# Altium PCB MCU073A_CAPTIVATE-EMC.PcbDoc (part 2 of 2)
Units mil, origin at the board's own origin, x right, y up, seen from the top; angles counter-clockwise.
Board outline 5374.02 x 3444.88 mil, 2 copper layers (Top Layer, Bottom Layer), stack 62 mil thick; 125 components, 86 nets, 448 pads, 154 vias.
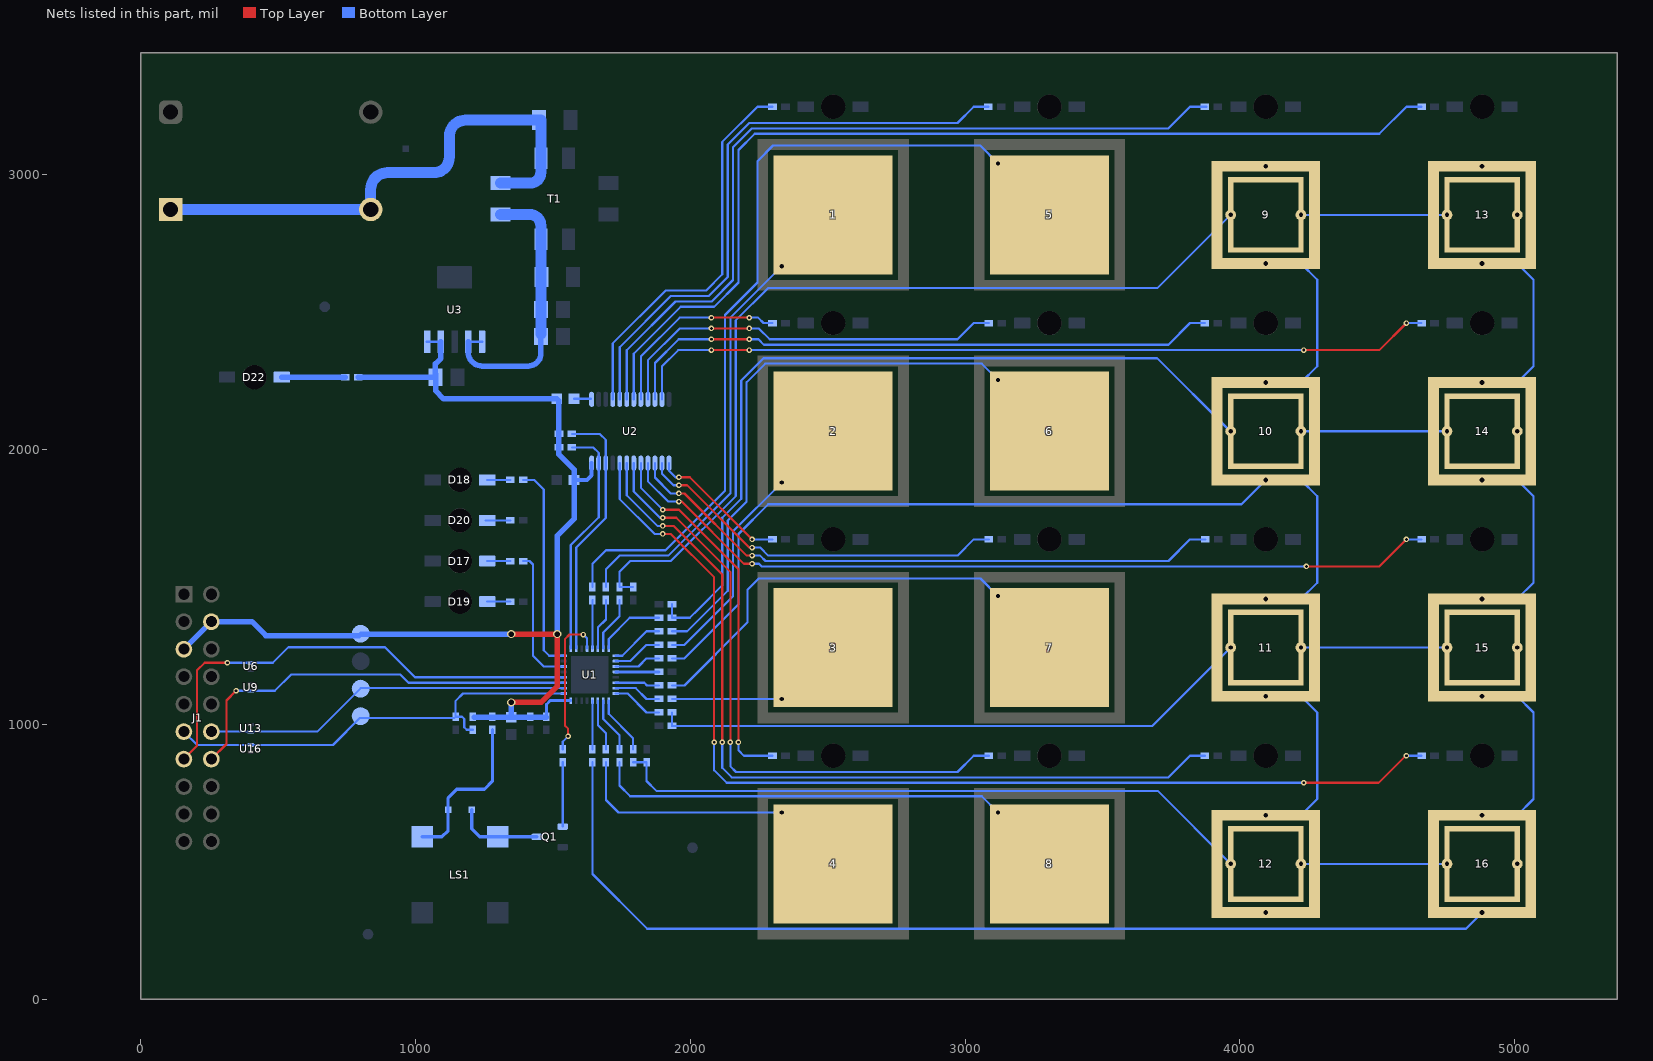
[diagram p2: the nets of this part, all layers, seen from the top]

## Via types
v1: diameter 30, hole 15, Top Layer to Bottom Layer, tented both sides, 102 vias
v2: diameter 20, hole 10, Top Layer to Bottom Layer, tented both sides, 34 vias
v3: diameter 30, hole 20, Top Layer to Bottom Layer, tented both sides, 13 vias
v4: diameter 19.68, hole 7.87, Top Layer to Bottom Layer, 5 vias

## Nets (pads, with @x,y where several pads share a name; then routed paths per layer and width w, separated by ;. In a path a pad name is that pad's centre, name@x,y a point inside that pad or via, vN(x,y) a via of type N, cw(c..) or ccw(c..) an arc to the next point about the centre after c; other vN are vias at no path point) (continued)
NetC12_1: C12.1 C13.1 C14.1 R39.2 T1.4 U3.1 U3.2 | length 1032.9
  Bottom Layer w10: U3.2@1191.73,2392.72 U3.1@1241.73,2392.72
  Bottom Layer w20: U3.2@1191.73,2392.72 1191.73,2354.13 ccw(c1241.73,2354.13) 1241.73,2304.13 1409.77,2304.13 ccw(c1409.77,2350.42) 1456.06,2350.42 C14.1@1456.06,2411.42
  Bottom Layer w40: R39.2@1309.05,2856.3 1414.56,2856.3 cw(c1414.56,2814.95) 1455.91,2814.95 T1.4@1455.91,2765.75 C14.1@1455.91,2421.42
NetD17_2: D17.2 R28.2 | length 83.7
  Bottom Layer w8: D17.2@1260.83,1594.49 R28.2@1344.49,1594.49
NetD18_2: D18.2 R36.2 | length 83.7
  Bottom Layer w8: D18.2@1260.83,1889.76 R36.2@1344.49,1889.76
NetD19_2: D19.2 R37.2 | length 83.7
  Bottom Layer w8: D19.2@1260.83,1446.85 R37.2@1344.49,1446.85
NetD20_2: D20.2 R38.2 | length 89.6
  Bottom Layer w8: D20.2@1254.92,1742.13 R38.2@1344.49,1742.13
NetD22_2: D22.2 R40.1 | length 231.3
  Bottom Layer w20: D22.2@512.79,2263.78 R40.1@744.09,2263.78
NetD23_1: D23.1 LS1.2 Q1.3 | length 317.6
  Bottom Layer w12: D23.1@1204.72,688.98 1204.72,619.59 1233.76,590.55 LS1.2@1299.21,590.55 Q1.3@1440.94,590.55
NetD23_2: D23.2 LS1.1 R42.1 | length 597.4
  Bottom Layer w12: LS1.1@1023.62,590.55 1095.97,590.55 1118.11,612.69 D23.2@1118.11,688.98 1118.11,732.28 1149.61,763.78 1250.76,763.78 1279.53,792.55 R42.1@1279.53,980.32
NetQ1_1: Q1.1 R43.2 | length 234.3
  Bottom Layer w8: Q1.1@1535.43,627.95 R43.2@1535.43,862.2
NetR1_1: R1.1 U1.13 | length 177.2
  Bottom Layer w8: U1.13@1643.7,1275.59 R1.1@1643.7,1452.76
NetR2_1: R2.1 U1.14 | length 189.4
  Bottom Layer w8: U1.14@1663.39,1275.59 1663.39,1352.35 1692.91,1381.88 R2.1@1692.91,1452.76
NetR3_1: R3.1 U1.15 | length 201.6
  Bottom Layer w8: U1.15@1683.07,1275.59 1683.07,1334.07 1742.13,1393.13 R3.1@1742.13,1452.76
NetR4_1: R4.1 U1.16 | length 250.3
  Bottom Layer w8: U1.16@1702.76,1275.59 1702.76,1311.02 1779.53,1387.79 R4.1@1885.83,1387.79
NetR5_1: R5.1 U1.17 | length 194.2
  Bottom Layer w8: U1.17@1728.35,1250 1751.97,1250 1840.55,1338.58 R5.1@1885.83,1338.58
NetR6_1: R6.1 U1.18 | length 181.9
  Bottom Layer w8: U1.18@1728.35,1230.31 1781.5,1230.31 1840.55,1289.37 R6.1@1885.83,1289.37
NetR7_1: R7.1 U1.19 | length 169.7
  Bottom Layer w8: U1.19@1728.35,1210.63 1811.02,1210.63 1840.55,1240.16 R7.1@1885.83,1240.16
NetR8_1: R8.1 U1.22 | length 161.6
  Bottom Layer w8: U1.22@1728.35,1151.57 1832.68,1151.57 1842.52,1141.73 R8.1@1885.83,1141.73
NetR9_1: R9.1 U1.23 | length 173.8
  Bottom Layer w8: U1.23@1728.35,1131.89 1801.18,1131.89 1840.55,1092.52 R9.1@1885.83,1092.52
NetR10_1: R10.1 U1.24 | length 186
  Bottom Layer w8: U1.24@1728.35,1112.2 1771.65,1112.2 1840.55,1043.31 R10.1@1885.83,1043.31
NetR11_1: R11.1 U1.25 | length 213.9
  Bottom Layer w7.87: U1.25@1702.76,1086.61 1702.76,1038.3 1791.34,949.71 R11.1@1791.34,909.45
NetR12_1: R12.1 U1.26 | length 201.6
  Bottom Layer w7.87: U1.26@1683.07,1086.61 1683.07,1019.41 1742.13,960.35 R12.1@1742.13,909.45
NetR13_1: R13.1 U1.27 | length 189.4
  Bottom Layer w7.87: U1.27@1663.39,1086.61 1663.39,997.6 1692.91,968.08
  Bottom Layer w8: R13.1@1692.91,909.45 1692.91,968.08
NetR14_1: R14.1 U1.28 | length 177.2
  Bottom Layer w8: R14.1@1643.7,909.45 U1.28@1643.7,1086.61
NetR17_1: R17.1 U2.4 | length 1424.7
  Bottom Layer w7.87: U2.4@1717.52,2183.07 1717.52,2386.81 1909.45,2578.74 2057.09,2578.74 2116.14,2637.8 2116.14,3120.08 2244.09,3248.03 R17.1@2299.21,3248.03
NetR19_1: R19.1 U2.5 | length 2176.4
  Bottom Layer w7.87: U2.5@1743.11,2183.07 1743.11,2373.03 1929.13,2559.06 2066.93,2559.06 2135.83,2627.95 2135.83,3110.24 2214.57,3188.98
  Bottom Layer w8: 2214.57,3188.98 2972.44,3188.98 3031.5,3248.03 R19.1@3084.65,3248.03
NetR20_1: R20.1 U2.6 | length 2938.3
  Bottom Layer w8: U2.6@1768.7,2183.07 1768.7,2362.21 1945.87,2539.37 2077.56,2539.37 2155.51,2617.32 2155.51,3100.39 2224.41,3169.29 3740.16,3169.29 3818.9,3248.03 R20.1@3872.8,3248.03 R20.1@3877.95,3248.03
NetR21_1: R21.1 U2.7 | length 3688.2
  Bottom Layer w8: U2.7@1794.29,2183.07 1794.29,2349.41 1964.56,2519.68 2086.61,2519.68 2175.2,2608.27 2175.2,3090.51 2234.29,3149.61 4507.87,3149.61 4606.3,3248.03 R21.1@4661.42,3248.03
NetR22_1: R22.1 U2.8 | length 711.8
  Top Layer w8: v2(2076.77,2480.32) v2(2214.57,2480.32)
  Bottom Layer w7.87: U2.8@1819.88,2183.07 1819.88,2338.94 1961.26,2480.32 v2(2076.77,2480.32)
  Bottom Layer w8: v2@2224.41,2480.32 v2(2214.57,2480.32) 2246.65,2480.32 2266.34,2460.63 R22.1@2299.21,2460.63
NetR23_1: R23.1 U2.9 | length 1481.6
  Top Layer w8: v2(2076.77,2440.94) v2(2214.57,2440.94)
  Bottom Layer w7.87: U2.9@1845.47,2183.07 1845.47,2324.8 1961.61,2440.94 v2(2076.77,2440.94)
  Bottom Layer w8: v2@2224.41,2440.94 v2(2214.57,2440.94) 2249.37,2440.94 2288.74,2401.57 2972.44,2401.57 3031.5,2460.63 R23.1@3086.61,2460.63
NetR24_1: R24.1 U2.10 | length 2210.3
  Top Layer w8: v2(2076.77,2401.57) v2(2214.57,2401.57)
  Bottom Layer w7.87: U2.10@1871.06,2183.07 1871.06,2314.96 1957.68,2401.57 v2(2076.77,2401.57)
  Bottom Layer w8: v2(2214.57,2401.57) 2247.96,2401.57 2267.65,2381.89 3740.16,2381.89 3818.9,2460.63 R24.1@3872.8,2460.63
NetR25_1: R25.1 U2.11 | length 2950.1
  Top Layer w8: v2(2076.77,2362.2) v2(2214.57,2362.2) ; v2(4232.28,2362.2) 4507.87,2362.2 v2(4606.3,2460.63)
  Bottom Layer w7.87: U2.11@1896.65,2183.07 1896.65,2303.15 1955.71,2362.2 v2(2076.77,2362.2)
  Bottom Layer w8: v2(2214.57,2362.2) v2(4232.28,2362.2) ; v2(4606.3,2460.63) R25.1@4661.42,2460.63
NetR26_1: R26.1 U2.13 | length 507.9
  Top Layer w8: v2(1958.66,1899.61) 1998.03,1899.61 v2(2224.41,1673.23)
  Bottom Layer w8: U2.13@1922.24,1950.79 1922.24,1923.26 1945.9,1899.61 v2(1958.66,1899.61) ; v2(2224.41,1673.23) R26.1@2299.02,1673.23
NetR27_1: R27.1 U2.14 | length 1376.3
  Top Layer w8: v2(1958.66,1870.08) 1988.19,1870.08 2214.57,1643.7 v2(2224.41,1643.7)
  Bottom Layer w8: U2.14@1896.65,1950.79 1896.65,1912.4 1938.98,1870.08 v2(1958.66,1870.08) ; v2(2224.41,1643.7) 2253.94,1643.7 2283.46,1614.17 2972.44,1614.17 3031.5,1673.23 R27.1@3086.61,1673.23
NetR29_1: R29.1 U2.15 | length 2213.7
  Top Layer w8: v2(1958.66,1840.55) 1978.35,1840.55 2204.72,1614.17 v2(2224.41,1614.17)
  Bottom Layer w8: U2.15@1871.06,1950.79 1871.06,1898.62 1929.13,1840.55 v2(1958.66,1840.55) ; v2(2224.41,1614.17) 2253.94,1614.17 2273.62,1594.49 3740.16,1594.49 3818.9,1673.23 R29.1@3874.02,1673.23
NetR30_1: R30.1 U2.16 | length 3051.1
  Top Layer w8: v2(1958.66,1811.02) 1968.5,1811.02 2194.88,1584.65 v2(2224.41,1584.65) ; v2(4242.13,1574.8) 4507.87,1574.8 v2(4606.3,1673.23)
  Bottom Layer w8: U2.16@1845.47,1950.79 1845.47,1884.84 1919.29,1811.02 v2(1958.66,1811.02) ; v2(2224.41,1584.65) 2249.87,1584.65 2259.71,1574.8 v2(4242.13,1574.8) ; v2(4606.3,1673.23) R30.1@4661.42,1673.23
NetR31_1: R31.1 U2.17 | length 1359.2
  Top Layer w8: v2(1899.61,1781.5) 1958.66,1781.5 2175.2,1564.96 v2(2175.2,935.04)
  Bottom Layer w8: U2.17@1819.88,1950.79 1819.88,1861.22 v2(1899.61,1781.5) ; v2(2175.2,935.04) 2175.2,905.51 2194.88,885.83 R31.1@2299.21,885.83
NetR32_1: R32.1 U2.18 | length 2257.5
  Top Layer w8: v2(1899.61,1751.97) 1948.82,1751.97 2145.67,1555.12 v2(2145.67,935.04)
  Bottom Layer w8: U2.18@1794.29,1950.79 1794.29,1847.44 1889.76,1751.97 v2(1899.61,1751.97) ; v2(2145.67,935.04) 2145.67,847.38 2166.27,826.77 2972.44,826.77 3031.5,885.83 R32.1@3086.61,885.83
NetR33_1: R33.1 U2.19 | length 3091.1
  Top Layer w8: v2(1899.61,1722.44) 1938.98,1722.44 2116.14,1545.28 v2(2116.14,935.04)
  Bottom Layer w8: U2.19@1768.7,1950.79 1768.7,1833.66 1879.92,1722.44 v2(1899.61,1722.44) ; v2(2116.14,935.04) 2116.14,841.89 2150.95,807.09 3740.16,807.09 3818.9,885.83 R33.1@3872.8,885.83
NetR34_2: R34.2 U2.1 | length 62
  Bottom Layer w8: R34.2@1576.77,2185.04 U2.1@1638.78,2185.04
NetR35_1: R35.1 U2.20 | length 3929
  Top Layer w8: v2(1899.61,1692.91) 1929.13,1692.91 2086.61,1535.43 v2(2086.61,935.04) ; v2(4232.28,787.4) 4505.18,787.4 4603.6,885.83 v2(4606.3,885.83)
  Bottom Layer w8: U2.20@1743.11,1950.79 1743.11,1819.88 1870.08,1692.91 v2(1899.61,1692.91) ; v2(2086.61,935.04) 2086.61,833.14 2132.36,787.4 v2(4232.28,787.4) ; v2(4606.3,885.83) R35.1@4661.42,885.83
NOISE: R28.1 U1.6 | length 501.2
  Bottom Layer w8: R28.1@1391.73,1594.49 1414.8,1594.49 1427.16,1582.13 1427.16,1250 1466.53,1210.63 U1.6@1539.37,1210.63
RUN: R36.1 U1.8 | length 755.6
  Bottom Layer w8: R36.1@1391.73,1889.76 1431.97,1889.76 1466.53,1855.2 1466.53,1269.68 1486.22,1250 U1.8@1539.37,1250
RX0: 1.RX R2.2 | length 1536.1
  Bottom Layer w8: R2.2@1692.91,1500 1692.91,1564.96 1742.13,1614.17 1919.29,1614.17 2145.67,1840.55 2145.67,2480.32 v1(2332.68,2667.32)
RX1: 2.RX R6.2 | length 782.6
  Bottom Layer w8: R6.2@1933.07,1289.37 1978.35,1289.37 2155.51,1466.54 2155.51,1702.76 v1(2332.68,1879.92)
RX2: 3.RX R9.2 | length 399.6
  Bottom Layer w8: R9.2@1933.07,1092.52 v1(2332.68,1092.52)
RX3: 4.RX R13.2 | length 796
  Bottom Layer w8: R13.2@1692.91,862.2 1692.91,724.96 1738.74,679.13 v1(2332.68,679.13)
RX4: 5.RX R1.2 | length 2851.8
  Bottom Layer w8: R1.2@1643.7,1500 1643.7,1584.65 1692.91,1633.86 1909.45,1633.86 2125.98,1850.39 2125.98,2490.16 2244.09,2608.27 2244.09,3049.73 2300.97,3106.61 3054.81,3106.61 v1(3120.08,3041.34)
RX5: 6.RX R5.2 | length 2019.5
  Bottom Layer w8: R5.2@1933.07,1338.58 1988.19,1338.58 2135.83,1486.22 2135.83,1742.13 2204.72,1811.02 2204.72,2245.5 2272.22,2312.99 3061.02,2312.99 v1(3120.08,2253.94)
RX6: 7.RX R8.2 | length 1444.3
  Bottom Layer w8: R8.2@1933.07,1141.73 1978.35,1141.73 2208.2,1371.58 2208.2,1490.29 2248.66,1530.75 3055.87,1530.75 v1(3120.08,1466.54)
RX7: 8.RX R12.2 | length 1503.4
  Bottom Layer w8: R12.2@1742.13,862.2 1742.13,777.56 1781.49,738.19 3061.02,738.19 v1(3120.08,679.13)
RX8: 9.RX 13.RX C6.2 R3.2 | length 3773.2
  Bottom Layer w7.87: 3700.79,2588.58 9.RX@3966.54,2854.33 ; 9.RX@4222.44,2854.33 13.RX@4753.94,2854.33
  Bottom Layer w8: C6.2@1791.34,1500 R3.2@1742.13,1500 1742.13,1555.12 1781.5,1594.49 1929.13,1594.49 2165.35,1830.71 2165.35,2470.47 2283.46,2588.58 3700.79,2588.58
RX9: 10.RX 14.RX C5.2 R4.2 | length 3518.7
  Bottom Layer w7.87: C5.2@1933.07,1437.01 R4.2@1933.07,1387.79 1998.03,1387.79 2027.56,1417.32 ; 10.RX@4222.44,2066.93 4751.97,2066.93 14.RX@4753.94,2068.9
  Bottom Layer w8: 2027.56,1417.32 2116.14,1505.91 2116.14,1751.97 2185.04,1820.87 2185.04,2251.69 2266.03,2332.68 3698.82,2332.68 3954.72,2076.77 10.RX@3976.38,2076.77
RX10: 11.RX 15.RX C8.2 R10.2 | length 2732.4
  Bottom Layer w8: R10.2@1933.07,1043.31 C8.2@1933.07,994.09 3681.1,994.09 11.RX@3966.54,1279.53 ; 11.RX@4222.44,1279.53 15.RX@4753.94,1279.53
RX11: 12.RX 16.RX C7.2 R11.2 | length 2900.1
  Bottom Layer w8: R11.2@1791.34,862.2 C7.2@1840.55,862.2 1840.55,793.69 1876.37,757.87 3700.79,757.87 12.RX@3966.54,492.13 ; 12.RX@4222.44,492.13 16.RX@4753.94,492.13
RXD: J1.13 U1.4 U6.2 | length 1758.1
  Top Layer w8: J1.13@156.63,873.62 204.72,921.71 204.72,1196.85 232.28,1224.41 v2(314.96,1224.41)
  Bottom Layer w8: v2(314.96,1224.41) 480.41,1224.41 537,1281 888.29,1281 998.03,1171.26 U1.4@1539.37,1171.26
SBWTCK: J1.12 pad.1 U1.2 U13.2 | length 1348.3
  Bottom Layer w8: J1.12@256.63,973.62 641.83,973.62 800.09,1131.89 U1.2@1539.37,1131.89
SBWTDIO: C9.2 J1.11 pad.2 R15.1 U1.1 U16.2 | length 1614.6
  Bottom Layer w8: J1.11@156.63,973.62 205.06,925.2 699.19,925.2 797.61,1023.62 1141.73,1023.62 C9.2@1145.67,1027.56 ; R15.1@1208.66,980.32 1186.06,980.32 1177.17,989.21 1177.17,1019.68 1169.29,1027.56 C9.2@1145.67,1027.56 ; U1.1@1539.37,1112.2 1172.41,1112.2 1145.67,1085.46 C9.2@1145.67,1027.56
SCL: R16.1 U1.10 U2.22 | length 936.3
  Bottom Layer w8: R16.1@1568.9,2057.09 1670.28,2057.09 1691.93,2035.43 U2.22@1691.93,1950.79 1691.93,1750.98 1584.65,1643.7 U1.10@1584.65,1275.59
SDA: R18.1 U1.9 U2.23 | length 860.2
  Bottom Layer w7.87: R18.1@1568.9,2007.87 1646.65,2007.87 1666.34,1988.19 U2.23@1666.34,1950.79
  Bottom Layer w8: U1.9@1564.96,1275.59 1564.96,1652.56 1666.34,1753.94 U2.23@1666.34,1950.79
SPEAKER: R43.1 U1.12 | length 544.6
  Top Layer w8: v2(1555.12,956.69) 1555.12,984.25 1543.31,996.06 1543.31,1310.04 1560.22,1326.96 v2(1610.24,1326.96)
  Bottom Layer w8: R43.1@1535.43,909.45 1535.43,937.01 v2(1555.12,956.69) ; v2(1610.24,1326.96) 1624.02,1313.18 U1.12@1624.02,1275.59
TX0: 9.TX 10.TX 11.TX 12.TX R7.2 | length 4794.1
  Bottom Layer w8: R7.2@1933.07,1240.16 1978.35,1240.16 2175.2,1437.01 2175.2,1692.91 2283.46,1801.18 4005.91,1801.18 10.TX@4094.49,1889.76 4222.44,1889.76 4281.5,1830.71 4281.5,1515.75 4222.44,1456.69 11.TX@4094.49,1456.69 ; 12.TX@4094.49,669.29 4222.44,669.29 4281.5,728.35 4281.5,1043.31 4222.44,1102.36 11.TX@4094.49,1102.36 ; 10.TX@4094.49,2244.09 4222.44,2244.09 4281.5,2303.15 4281.5,2618.11 4222.44,2677.17 9.TX@4094.49,2677.17
TX1: 13.TX 14.TX 15.TX 16.TX R14.2 | length 5965.7
  Bottom Layer w7.87: 1861.62,255.91 1978.35,255.91
  Bottom Layer w8: R14.2@1643.7,862.2 1643.7,455.53 1843.32,255.91 1861.62,255.91 ; 1978.35,255.91 4822.83,255.91 16.TX@4881.89,314.96 ; 16.TX@4881.89,669.29 5009.84,669.29 5068.9,728.35 5068.9,1043.31 5009.84,1102.36 15.TX@4881.89,1102.36 ; 15.TX@4881.89,1456.69 5009.84,1456.69 5068.9,1515.75 5068.9,1830.71 5009.84,1889.76 14.TX@4881.89,1889.76 ; 14.TX@4881.89,2244.09 5009.84,2244.09 5068.9,2303.15 5068.9,2618.11 5009.84,2677.17 13.TX@4881.89,2677.17
TXD: J1.14 U1.3 U9.2 | length 1515.2
  Top Layer w8: J1.14@256.63,873.62 311.52,928.51 311.52,1087.11 v2(346.46,1122.05)
  Bottom Layer w8: v2(346.46,1122.05) 487.2,1122.05 546.26,1181.1 944.88,1181.1 974.41,1151.57 U1.3@1539.37,1151.57
VCC_3V3: C1.1 C2.1 C3.2 C10.1 C15.1 J1.4 J1.5 pad.3 R15.2 R16.2 R18.2 R34.1 R40.2 R42.2 U1.32 U2.24 U3.4 U3.5 | length 4257.4
  Top Layer w20: v3(1348.11,1080) 1456.93,1080 1515.75,1138.81 v3(1515.75,1328.74) v3(1348.43,1328.74)
  Bottom Layer w10: U3.5@1041.73,2392.72 U3.4@1091.73,2392.72 ; C3.2@1476.38,1025.61 C3.2@1476.38,1027.56 1476.38,1072.83 1490.16,1086.61 U1.32@1564.96,1086.61
  Bottom Layer w15: C10.1@1576.77,1889.76 1624.02,1889.76 1640.75,1906.5 U2.24@1640.75,1950.79
  Bottom Layer w20: J1.5@156.63,1273.62 J1.4@256.63,1373.62 404.14,1373.62 454.92,1322.83 pad.3@792.83,1322.83 ; R40.2@791.34,2263.78 C15.1@1072.2,2263.78 1072.2,2312.36 1091.73,2331.89 U3.4@1091.73,2392.72 ; pad.3@801.26,1328.74 v3(1348.43,1328.74) ; C15.1@1072.83,2273.62 1072.83,2214.57 1102.36,2185.04 R34.1@1513.78,2185.04 1521.65,2177.17 R16.2@1521.65,2057.09 R18.2@1521.65,2007.87 1521.65,1982.28 1576.77,1927.17 C10.1@1576.77,1889.76 1576.77,1747.85 1515.75,1686.83 v3(1515.75,1328.74) ; R15.2@1212.6,1025.59 1244.09,1025.59 C1.1@1348.42,1025.59 C3.2@1476.38,1025.61 ; C1.1@1348.11,1025.92 v3(1348.11,1080)
VCC_IN: C11.2 D21.2 JP1.1 JP1.2 R39.1 T1.1 | length 1955.9
  Bottom Layer w40: JP1.1@108.27,2874.02 836.61,2874.02 836.61,2947.54 cw(c896.94,2947.54) 896.94,3007.87 1066.33,3007.87 ccw(c1066.33,3064.21) 1122.68,3064.21 1122.68,3140.39 cw(c1181.1,3140.39) 1181.1,3198.82 1455.91,3198.82 T1.1@1455.91,3061.02 1455.91,3009.06 cw(c1417.32,3009.06) 1417.32,2970.47 R39.1@1309.05,2970.47
VREG: C4.1 U1.20 | length 157.5
  Bottom Layer w10: U1.20@1728.35,1190.95 C4.1@1885.83,1190.94
pads on no net: D1. D2. D3. D4. D5. D6. D7. D8. D9. D10. D11. D12. D13. D14. D15. D16. D17. D18. D19. D20. D22. FID1.1 FID2.1 FID3.1 H1.0 H2.0 H3.0 H4.0 J1.3 J1.6 J1.9 J1.10 J1.15 J1.16 J1.17 J1.18 LS1.3 LS1.4 U1. U1.11 U1.21 U1.29 U1.30 U6.1S U6.2S U9.1S U9.2S U13.1S U13.2S U16.1S U16.2S

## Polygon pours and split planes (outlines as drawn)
GND on Top Layer "TOP_LAYER_GND_P002" (solid, remove dead copper, pour order 2): 1879.92,3346.46 5275.59,3346.46 5275.59,98.43 78.74,98.42 78.74,2677.16 1879.92,2677.17
GND on Bottom Layer "BOTTOM_LAYER_GND_P010" (solid, remove dead copper, pour order 10): 2096.46,98.42 2096.46,2677.17 78.74,2677.16 78.74,98.42
GND on Bottom Layer "BOTTOM_LAYER_GND_P008" (hatched 45Degree grid 64 track 8, remove dead copper, pour order 8): 5275.59,98.43 5275.59,3346.46 1879.92,3346.46 1879.92,2627.95 1998.03,2627.95 1998.03,98.43
GND on Bottom Layer "BOTTOM_LAYER_GND_P004" (solid, remove dead copper, pour order 4): 5275.59,98.43 5275.59,3346.46 3710.63,3346.46 3710.63,1998.05 3710.63,98.43

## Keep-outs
Keep-Out Layer:
  text ".Layer_Name" at 498.26,-858.49 h60

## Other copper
Top Layer:
  text ".Layer_Name" at 498.26,-858.49 h60
Bottom Layer:
  text ".Layer_Name" at 498.26,-858.49 h60

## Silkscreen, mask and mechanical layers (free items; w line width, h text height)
Top Overlay:
  text "'.PRJ_Number'.PCB_Rev" at 1262.8,2877.95 h108.27
  text "5VDC ~ 20VDC" at 196.85,2582.68 h85
  text "POWER" at 511.81,2231.97 h100
  text "RUN" at 1283.46,1854.33 h100
  text "DETECT" at 1283.46,1706.69 h100
  text "NOISE" at 1283.46,1559.06 h100
  text "FAULT" at 1283.46,1411.42 h100
  text "CAPTIVATE-EMC VERSION A" at 3553.15,59.06 h125
  text ".Layer_Name" at 498.26,-858.49 h60
Bottom Overlay:
  lines w10: 900.2,590.55 950.2,590.55 ; 925.2,565.55 925.2,615.55 ; 5374.02,3435.04 5374.02,3444.88
  text ".Layer_Name" at 498.26,-858.49 h60
Top Paste:
  text ".Layer_Name" at 498.26,-858.49 h60
Bottom Paste:
  text ".Layer_Name" at 498.26,-858.49 h60
Top Solder:
  text ".Layer_Name" at 498.26,-858.49 h60
  text ".Layer_Name" at 498.26,-858.49 h60
Bottom Solder:
  text ".Layer_Name" at 498.26,-858.49 h60
Drill Guide:
  text ".Layer_Name" at 498.26,-858.49 h60
M1 Board Outline:
  the board outline again, w10
  text ".Layer_Name" at 498.26,-858.49 h60
M2 Board Dimensions:
  rectangle: 46.26,-400 421.26,-275
  rectangle: -78.74,-275 46.26,-150
  lines w7: -78.74,-275 921.26,-275 ; 46.26,-400 46.26,-150 ; 171.26,-400 171.26,-150 ; 421.26,-400 421.26,-150 ; 671.26,-400 671.26,-150 ; -78.74,-400 -78.74,-150 921.26,-150 921.26,-400 -78.74,-400
  text ".Layer_Name" at 498.26,-858.49 h60
M3 3D STEP Top:
  text ".Layer_Name" at 498.26,-858.49 h60
M4 3D STEP Bottom:
  text ".Layer_Name" at 498.26,-858.49 h60
M5 Assembly Top:
  lines w10: -370.74,-930.17 6229.26,-930.17 ; -370.74,-726.83 6231.26,-726.83 ; -370.74,-523.5 -370.74,-1133.5 3634.26,-1133.5 6231.26,-1133.5 6231.26,-523.5 -370.24,-523.5 -370.24,-1133.5 1205.26,-1133.5 ; 2094.26,-1133.5 2094.26,-523.5 ; 3361.26,-726.83 3361.26,-523.5 ; 4201.26,-726.83 4201.26,-523.5 ; 4823.26,-1140 4823.26,-937.17
  text "COMPONENTS MARKED 'DNP' SHOULD NOT BE POPULATED." at 1074.76,-318.5 h60
  text "ASSEMBLY VARIANT:" at 1074.26,-434 h60
  text ".VariantName" at 2110.26,-434 h60
  text "PCB VIEWED FROM TOP SIDE" at -307.24,-655.67 h60
  text "BOARD #:" at 2169.26,-655.67 h60
  text ".PRJ_Number" at 2714.76,-655.67 h60
  text "REV:" at 3559.26,-655.67 h60
  text ".PCB_Rev" at 3850.76,-655.67 h60
  text "SVN REV:" at 4397.26,-655.67 h60
  text ".VersionControl_RevNumber" at 4903.26,-655.67 h60
  text "TID #:" at 2169.26,-859 h60
  text ".TID" at 2714.76,-859 h60
  text "PLOT NAME =" at -307.24,-1064.34 h60
  text ".plot_File_Name" at 498.26,-1064.34 h60
  text "GENERATED    :" at 2171.26,-1064.34 h60
  text ".Print_Date" at 3040.76,-1064.34 h60
  text ".Print_Time" at 3769.76,-1064.34 h60
  text "TEXAS INSTRUMENTS" at 5034.26,-1064.34 h60
M6 Assembly Bottom:
  lines w10: -371.24,-727.33 6230.76,-727.33 ; -369.24,-930.67 6230.76,-930.67 ; 1036.76,-1140.5 1036.76,-937.67 ; 1658.76,-727.33 1658.76,-524 ; 2498.76,-727.33 2498.76,-524 ; 3765.76,-1134 3765.76,-524 ; 4654.76,-1134 6230.26,-1134 6230.26,-524 -371.24,-524 -371.24,-1134 2225.76,-1134 6230.76,-1134 6230.76,-524
  text "COMPONENTS MARKED 'DNP' SHOULD NOT BE POPULATED." at 6023.26,-318 h60
  text ".VariantName" at 4979.26,-434 h60
  text "ASSEMBLY VARIANT:" at 6018.26,-434 h60
  text ".VersionControl_RevNumber" at 956.76,-656.17 h60
  text "SVN REV:" at 1462.76,-656.17 h60
  text ".PCB_Rev" at 2009.26,-656.17 h60
  text "REV:" at 2300.76,-656.17 h60
  text ".PRJ_Number" at 3145.26,-656.17 h60
  text "BOARD #:" at 3690.76,-656.17 h60
  text "PCB VIEWED FROM BOTTOM SIDE" at 6167.26,-656.17 h60
  text ".TID" at 3145.26,-859.5 h60
  text "TID #:" at 3690.76,-859.5 h60
  text "TEXAS INSTRUMENTS" at 825.76,-1064.84 h60
  text ".Print_Time" at 2090.26,-1064.84 h60
  text ".Print_Date" at 2819.26,-1064.84 h60
  text "GENERATED    :" at 3688.76,-1064.84 h60
  text ".plot_File_Name" at 5361.76,-1064.84 h60
  text "PLOT NAME =" at 6167.26,-1064.84 h60
M9 Title Sheet:
  drawing of 57 lines, arcs and shapes, not listed
  text "1" at 661.1,8036.5 h70
  text "2" at 3156.76,8036.5 h70
  text "3" at 5646.1,8036.5 h70
  text "4" at 8152.77,8036.5 h70
  text "5" at 10651.76,8036.5 h70
  text "6" at 13156.76,8036.5 h70
  text "A" at -495.24,6893.5 h70
  text "A" at 14304.76,6893.5 h70
  text "B" at -495.24,4513.5 h70
  text "B" at 14304.76,4513.5 h70
  text "C" at -495.24,2138.5 h70
  text "C" at 14304.76,2138.5 h70
  text "PROJECT TITLE:" at 11264.76,277.5 h45
  text ".PRJ_Title" at 11314.76,144.17 h70
  text "DESIGNED FOR:" at 11264.76,-23.5 h45
  text ".PRJ_Customer" at 11314.76,-163.5 h70
  text "D" at -495.24,-231.5 h70
  text "D" at 14304.76,-231.5 h70
  text "FILE NAME:" at 11264.76,-323.5 h45
  text ".PCB_File_Name_No_Path" at 11314.76,-443.5 h70
  text "Texas Instruments (TI) and/or its licensors do not warrant the accuracy or completeness of this specification" at 6295.26,-605.34 h45
  text "ENGINEER:" at 11264.76,-613.5 h45
  text "LAYOUT BY:" at 12769.76,-613.5 h45
  text "or any information contained therein. TI and/or its licensors do not warrant that this design will meet" at 6250.27,-718 h45
  text ".PRJ_Engineer" at 11314.76,-768.49 h70
  text ".PCB_Layout" at 12820.26,-768.49 h70
  text "the specifications, will be suitable for your application or fit for any particular purpose, or will operate in" at 6250.27,-830.67 h45
  text ".Layer_Name" at 498.26,-858.49 h60
  text "ALTIUM DESIGNER VERSION:" at 12769.76,-923.5 h45
  text "an implementation. TI and/or its licensors do not warrant that the design is production worthy. You should" at 6250.27,-943.33 h45
  text "completely validate and test your design implementation to confirm the system functionality for your application." at 6295.26,-1056 h45
  text ".print_Scale" at 11314.76,-1056.83 h70
  text ".Application_BuildNumber" at 12820.26,-1056.83 h70
  text "1" at 661.1,-1263.5 h70
  text "2" at 3156.76,-1263.5 h70
  text "3" at 5646.1,-1263.5 h70
  text "4" at 8152.77,-1263.5 h70
  text "5" at 10651.76,-1263.5 h70
  text "6" at 13156.76,-1263.5 h70
M10 Fab Notes:
  drawing of 189 lines, arcs and shapes, not listed
  text "DESIGN INFORMATION" at 12303.28,6356.17 h60
  text "MIN. TRACK WIDTH:" at 11658.72,6224.05 h60
  text "8" at 12754.96,6224.05 h60
  text "MIL" at 12909.72,6224.05 h60
  text "MIN. CLEARANCE:" at 11658.72,6099.92 h60
  text "0.2" at 12694.96,6099.93 h60
  text "mm" at 12909.72,6099.92 h60
  text "MIN. VIA PAD SIZE:" at 11658.72,5975.8 h60
  text "24" at 12724.97,5975.8 h60
  text "MIL" at 12909.72,5975.8 h60
  text "0.05mm (2MIL)" at 12353.72,5845.9 h60
  text "MINIMUM ANNULAR RING" at 11329.49,5837.67 h60
  text "EXTERNAL" at 13061.72,5837.67 h60
  text "PER" at 11529.49,5727.55 h60
  text "IPC-D-275 CLASS 2 LEVEL C" at 11749.49,5727.54 h60
  text "MIL, HOLES" at 13237.72,5627.07 h60
  text "+/-" at 12845.26,5618.48 h60
  text "+/-" at 13699.26,5618.48 h60
  text "REGISTRATION TOLERANCES:" at 11329.49,5617.42 h60
  text "METAL" at 12529.26,5617.42 h60
  text "5" at 13105.46,5617.42 h60
  text "3" at 13938.46,5617.42 h60
  text "MIL" at 14054.72,5617.42 h60
  text "HOLE SIZE TOLERANCE (UNLESS OTHERWISE SPECIFIED):" at 11329.49,5519.1 h60
  text "+/-" at 13699.26,5516.23 h60
  text "3" at 13938.46,5515.17 h60
  text "MIL" at 14054.72,5515.17 h60
  text "MATERIAL:" at 11254.72,5377.52 h60
  text "FR-4 High Tg" at 12241.16,5249 h60
  text "X" at 12096.72,5241.01 h60
  text "FR-408" at 11675.72,5236.49 h60
  text "OTHER" at 13163.72,5236.49 h60
  text "62 MIL (1.6mm) +/-10%" at 11995.82,5093.46 h60
  text "X" at 11875.72,5091.01 h60
  text "THICKNESS:" at 11329.49,5085.24 h60
  text "OTHER" at 13280.72,5085.24 h60
  text "TOLERANCE:" at 11329.49,4946.92 h60
  text "X" at 12177.72,4946.92 h60
  text "ANSI IPC-6012 TYPE 3 CLASS 2" at 12355.74,4946.92 h60
  text "OTHER +/-" at 12355.72,4802.73 h60
  text "BOW & TWIST:" at 11329.49,4657.54 h60
  text "X" at 12177.72,4657.54 h60
  text "ANSI IPC-6012 TYPE 3 CLASS 2" at 12355.74,4657.54 h60
  text "OTHER +/-" at 12355.72,4510.85 h60
  text "DRILLING:" at 11254.72,4380.23 h60
  text "NC_DRILL FILES" at 13015.72,4275.04 h60
  text "REFERENCE:" at 11329.49,4271.1 h60
  text "X" at 11986.72,4271.01 h60
  text "AS SHOWN" at 12164.72,4271.1 h60
  text "X" at 12887.72,4271.1 h60
  text "OTHER" at 13313.72,4128.85 h60
  text "PTH COPPER THICKNESS:" at 11329.17,4125.32 h60
  text "X" at 12468.4,4125.32 h60
  text "20-30 um" at 12596.4,4125.32 h60
  text "BOARD FINISH:" at 11254.72,3977.73 h60
  text "SILKSCREEN:" at 11409.94,3867.6 h60
  text "X" at 12367.72,3867.6 h60
  text "TOP" at 12484.72,3867.6 h60
  text "X" at 12877.72,3867.6 h60
  text "BOTTOM" at 12995.72,3867.6 h60
  text "SILKSCREEN COLOR:" at 11409.94,3712.41 h60
  text "X" at 12366.72,3712.41 h60
  text "WHITE" at 12484.72,3712.41 h60
  text "OTHER" at 12995.72,3712.41 h60
  text "X" at 13084.65,3570.87 h60
  text "GREEN" at 12615.72,3568.96 h60
  text "OTHER" at 13233.72,3568.96 h60
  text "BLACK" at 13579.72,3568.9 h60
  text "SOLDER RESIST COLOR:" at 11409.94,3562.1 h60
  text "X" at 12497.72,3414.71 h60
  text "MATTE" at 12615.72,3414.71 h60
  text "SEMI-GLOSS" at 13233.26,3414.07 h60
  text "IMMERSION GOLD (ENIG)" at 12315.72,3241.94 h60
  text "ENEPIG" at 13653.26,3234.72 h60
  text "SURFACE FINISH:" at 11254.72,3233.72 h60
  text "X" at 12137.72,3233.72 h60
  text "IMM. TIN/SILVER OR EQUIV" at 11584.26,3096.4 h60
  text "OTHER" at 13015.72,3092.47 h60
  text "ARRAY/PANEL:" at 11254.72,2937.09 h60
  text "CUT AND TRIM PER M1 BOARD OUTLINE" at 12315.72,2928.87 h60
  text "N.C. ROUTE" at 12315.72,2792.9 h60
  text "X" at 13003.72,2792.9 h60
  text "V. SCORE" at 13181.72,2792.9 h60
  text "CERTIFICATION:" at 11254.72,2663.77 h60
  text "MATERIALS AND WORKMANSHIP FOR ALL PCBS" at 11979.72,2663.77 h60
  text "TO MEET OR EXCEED THE REQUIREMENTS OF:" at 11979.72,2569.71 h60
  text "X" at 11617.23,2441.08 h60
  text "ANSI IPC-A-600F CLASS ->" at 11745.22,2441.08 h60
  text "X" at 13393.23,2441.08 h60
  text "2" at 13503.22,2441.08 h60
  text "1" at 13188.22,2439.58 h60
  text "3" at 13857.22,2439.58 h60
  text "X" at 12429.23,2293.39 h60
  text "RoHS" at 12557.22,2293.39 h60
  text "OTHER" at 13201.62,2293.39 h60
  text "PER ORDER" at 13598.68,2293.39 h60
  text "ALL BOARDS MUST MEET OR EXCEED UL94-V0 REQUIREMENTS." at 11282.26,2139.57 h60
  text "PCB MUST BEAR THE UL94V-0 UL REGISTERED MATERIAL ID NUMBER" at 11282.26,2023.5 h60
  text "ADDITIONAL REQUIREMENTS:" at 11254.72,1854.08 h60
  text "MICROSECTION:" at 11329.49,1746.95 h60
  text "YES" at 12235.22,1746.95 h60
  text "REQUIRED" at 13096.72,1602.62 h60
  text "BARE BOARD ELEC. TEST:" at 11329.49,1599.76 h60
  text "NONE" at 12635.22,1599.76 h60
  text "X" at 12978.72,1599.76 h60
  text "PER ORDER" at 13688.72,1599.76 h60
  text "XX MIL VIAS REQUIRE NON-CONDUCTIVE FILL AND PLANARIZE" at 11497.64,1394.82 h59
  text "XX MIL VIAS REQUIRE CONDUCTIVE FILL AND PLANARIZE" at 11505.64,1290.84 h60
  text "OUTER XX MIL TRACES REQUIRE 50 OHM SINGLE-ENDED IMPEDANCE" at 11504.65,1127.46 h58
  text "LAYER 2 & 3 (INNER LAYERS) XX MIL WIDE, XX MIL SPACE / TRACES REQUIRE 100 OHM DIFFERENTIAL IMPEDANCE" at 11496.65,891.74 h60
  text ".Layer_Name" at 498.26,-858.49 h60
M11 Gerber Information:
  lines w10: -370.74,-930.17 6229.26,-930.17 ; -370.74,-726.83 6231.26,-726.83 ; -370.74,-523.5 -370.74,-1133.5 3634.26,-1133.5 6231.26,-1133.5 6231.26,-523.5 -370.24,-523.5 -370.24,-1133.5 1205.26,-1133.5 ; 2094.26,-1133.5 2094.26,-523.5 ; 3361.26,-726.83 3361.26,-523.5 ; 4201.26,-726.83 4201.26,-523.5 ; 4823.26,-1140 4823.26,-937.17
  text "ALL ARTWORK VIEWED FROM TOP SIDE" at -307.24,-655.67 h60
  text "BOARD #:" at 2169.26,-655.67 h60
  text ".PRJ_Number" at 2714.76,-655.67 h60
  text "REV:" at 3559.26,-655.67 h60
  text ".PCB_Rev" at 3850.76,-655.67 h60
  text "SVN REV:" at 4397.26,-655.67 h60
  text ".VersionControl_RevNumber" at 4903.26,-655.67 h60
  text "LAYER NAME =" at -307.24,-858.49 h60
  text "TID #:" at 2169.26,-859 h60
  text ".TID" at 2714.76,-859 h60
  text "PLOT NAME =" at -307.24,-1064.34 h60
  text ".plot_File_Name" at 498.26,-1064.34 h60
  text "GENERATED    :" at 2171.26,-1064.34 h60
  text ".Print_Date" at 3040.76,-1064.34 h60
  text ".Print_Time" at 3769.76,-1064.34 h60
  text "TEXAS INSTRUMENTS" at 5034.26,-1064.34 h60
M12 Stackup:
  drawing of 191 lines, arcs and shapes, not listed
  text "Layer" at 9719.1,7380 h60
  text "Name" at 10129.02,7380 h60
  text "Material" at 11058.76,7380 h60
  text "Thickness" at 11918.53,7380 h60
  text "Constant" at 12568.36,7380 h60
  text "Board Layer Stack" at 13138.22,7380 h60
  text "1" at 9719.1,7260 h60
  text "Top Overlay" at 10129.02,7260 h60
  text "2" at 9719.1,7140 h60
  text "Top Solder" at 10129.02,7140 h60
  text "Solder Resist" at 11058.76,7140 h60
  text "0.40mil" at 11918.53,7140 h60
  text "3.5" at 12568.36,7140 h60
  text "3" at 9719.1,7020 h60
  text "Top Layer" at 10129.02,7020 h60
  text "Copper" at 11058.76,7020 h60
  text "1.40mil" at 11918.53,7020 h60
  text "4" at 9719.1,6900 h60
  text "Dielectric1" at 10129.02,6900 h60
  text "FR-4" at 11058.76,6900 h60
  text "59.20mil" at 11918.53,6900 h60
  text "4.8" at 12568.36,6900 h60
  text "5" at 9719.1,6780 h60
  text "Bottom Layer" at 10129.02,6780 h60
  text "Copper" at 11058.76,6780 h60
  text "1.40mil" at 11918.53,6780 h60
  text "6" at 9719.1,6660 h60
  text "Bottom Solder" at 10129.02,6660 h60
  text "Solder Resist" at 11058.76,6660 h60
  text "0.40mil" at 11918.53,6660 h60
  text "3.5" at 12568.36,6660 h60
  text "7" at 9719.1,6540 h60
  text "Bottom Overlay" at 10129.02,6540 h60
  text ".Layer_Name" at 498.26,-858.49 h60
M13 Component Bodies Top:
  text ".Layer_Name" at 498.26,-858.49 h60
M14 Component Bodies Bottom:
  text ".Layer_Name" at 498.26,-858.49 h60
M15 Courtyards Top:
  text ".Layer_Name" at 498.26,-858.49 h60
M16 Courtyards Bottom:
  text ".Layer_Name" at 498.26,-858.49 h60
Drill Drawing:
  circle w10: c6667.05,4868.94 r16.56
  circle w10: c6667.05,4868.94 r27.59
  circle w10: c6667.05,4372.23 r27.59
  lines w10: 6639.45,4220.46 6639.45,4234.26 6653.25,4248.06 6639.45,4261.85 6639.45,4275.65 6653.25,4275.65 6667.05,4261.85 6680.85,4275.65 6694.64,4275.65 6694.64,4261.85 6680.85,4248.06 6694.64,4234.26 6694.64,4220.46 6680.85,4220.46 6667.05,4234.26 6653.25,4220.46 6639.45,4220.46 ; 6639.45,4468.81 6694.64,4468.81 6694.64,4524 6639.45,4524 6639.45,4468.81 ; 6639.45,4606.79 6653.25,4606.79 6667.05,4592.99 6680.85,4606.79 6694.64,4606.79 6680.85,4620.58 6694.64,4634.38 6680.85,4634.38 6667.05,4648.18 6653.25,4634.38 6639.45,4634.38 6653.25,4620.58 6639.45,4606.79 ; 6639.45,4717.16 6667.05,4730.96 6694.64,4717.16 6680.85,4744.76 6694.64,4772.35 6667.05,4758.56 6639.45,4772.35 6653.25,4744.76 6639.45,4717.16 ; 6639.45,5020.71 6694.64,5020.71 6667.05,4965.52 6639.45,5020.71 ; 6639.45,5117.29 6667.05,5089.69 6694.64,5117.29 6667.05,5144.88 6639.45,5117.29 ; 6639.45,5213.87 6694.64,5213.87 6694.64,5269.06 6639.45,5269.06 6639.45,5213.87 ; 6650.49,4479.85 6683.61,4479.85 6683.61,4512.96 6650.49,4512.96 6650.49,4479.85 ; 6650.49,5009.67 6683.61,5009.67 6667.05,4976.55 6650.49,5009.67
  lines w12: 6589.42,4183.21 9819.94,4183.21 ; 6589.42,5300.79 9819.94,5300.79 ; 6927.28,4059.03 6927.28,5424.97 ; 7259.28,4059.03 7259.28,5424.97 ; 7895.84,4059.03 7895.84,5424.97 ; 8154.94,4059.03 8154.94,5424.97 ; 8530.1,4059.03 8530.1,5424.97 ; 9253.48,4059.03 9253.48,5424.97 ; 6589.42,4059.03 9819.94,4059.03 9819.94,5424.97 6589.42,5424.97 6589.42,4059.03
  text "Symbol" at 6663.92,5338.04 h72
  text "Quantity" at 6964.53,5338.04 h72
  text "Finished Hole Size" at 7296.53,5338.04 h72
  text "Plated" at 7933.09,5338.04 h72
  text "Hole Type" at 8192.2,5338.04 h72
  text "Drill Layer Pair" at 8567.35,5338.04 h72
  text "Hole Tolerance" at 9290.73,5338.04 h72
  text "21" at 6964.53,5213.87 h60
  text "88.58mil (2.250mm)" at 7296.53,5213.87 h60
  text "NPTH" at 7933.09,5213.87 h60
  text "Round" at 8192.2,5213.87 h60
  text "Top Layer - Bottom Layer" at 8567.35,5213.87 h60
  text "5" at 6964.53,5089.69 h60
  text "7.87mil (0.200mm)" at 7296.53,5089.69 h60
  text "PTH" at 7933.09,5089.69 h60
  text "Round" at 8192.2,5089.69 h60
  text "Top Layer - Bottom Layer" at 8567.35,5089.69 h60
  text "34" at 6964.53,4965.52 h60
  text "10.00mil (0.254mm)" at 7296.53,4965.52 h60
  text "PTH" at 7933.09,4965.52 h60
  text "Round" at 8192.2,4965.52 h60
  text "Top Layer - Bottom Layer" at 8567.35,4965.52 h60
  text "102" at 6964.53,4841.34 h60
  text "15.00mil (0.381mm)" at 7296.53,4841.34 h60
  text "PTH" at 7933.09,4841.34 h60
  text "Round" at 8192.2,4841.34 h60
  text "Top Layer - Bottom Layer" at 8567.35,4841.34 h60
  text "16" at 6964.53,4717.16 h60
  text "15.75mil (0.400mm)" at 7296.53,4717.16 h60
  text "PTH" at 7933.09,4717.16 h60
  text "Round" at 8192.2,4717.16 h60
  text "Top Layer - Bottom Layer" at 8567.35,4717.16 h60
  text "16" at 6964.53,4592.99 h60
  text "17.72mil (0.450mm)" at 7296.53,4592.99 h60
  text "PTH" at 7933.09,4592.99 h60
  text "Round" at 8192.2,4592.99 h60
  text "Top Layer - Bottom Layer" at 8567.35,4592.99 h60
  text "13" at 6964.53,4468.81 h60
  text "20.00mil (0.508mm)" at 7296.53,4468.81 h60
  text "PTH" at 7933.09,4468.81 h60
  text "Round" at 8192.2,4468.81 h60
  text "Top Layer - Bottom Layer" at 8567.35,4468.81 h60
  text "20" at 6964.53,4344.64 h60
  text "40.16mil (1.020mm)" at 7296.53,4344.64 h60
  text "PTH" at 7933.09,4344.64 h60
  text "Round" at 8192.2,4344.64 h60
  text "Top Layer - Bottom Layer" at 8567.35,4344.64 h60
  text "4" at 6964.53,4220.46 h60
  text "55.00mil (1.397mm)" at 7296.53,4220.46 h60
  text "PTH" at 7933.09,4220.46 h60
  text "Round" at 8192.2,4220.46 h60
  text "Top Layer - Bottom Layer" at 8567.35,4220.46 h60
  text "231 Total" at 6964.53,4096.28 h60
  text ".Layer_Name" at 498.26,-858.49 h60
M17 Embedded Cavity:
  text ".Layer_Name" at 498.26,-858.49 h60
M18 Embedded Assembly:
  text ".Layer_Name" at 498.26,-858.49 h60
M19 Embedded Keepout:
  text ".Layer_Name" at 498.26,-858.49 h60

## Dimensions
0,3444.88 to 0,0 on M2 Board Dimensions
5374.02,0 to 0,0 on M2 Board Dimensions
-78.74,-400 to 921.26,-400 on M2 Board Dimensions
